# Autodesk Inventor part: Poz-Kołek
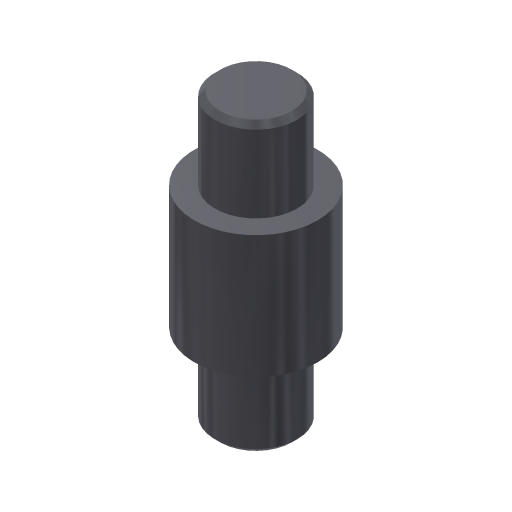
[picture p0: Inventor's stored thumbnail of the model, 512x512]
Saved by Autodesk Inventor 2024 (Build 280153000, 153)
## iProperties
Company: ATC
Shininess: 20.0
Angle Display Precision: 2
Document Length Units: 11269
Document Angle Units: 11279
Document Time Units: 11290
Document Mass Units: 11283
Document Length Units Precision: 3
Document Angle Units Precision: 2
Created: 2023-03
Part Number: Poz-Kołek
Material: Standardowy
Document SubType Name: Modelowanie
Designer: Andrzej Jaskulski
Density: 1 g/cm^3
Appearance: Metal-stal (polerowana)
Checked By: A.J.
Engr Approved By: Andrzej Jaskulski
Mfg Approved By: Andrzej Jaskulski
Authority: A.J.
Density: 0.0
Volumn: 0.0
Area: 0.0
PropertySet Name: Model Information
Control State: 0
Master: False
Checked Out: False
Title: A.J.: Kurs R2024-MEP
Author: Andrzej Jaskulski
Revision Number: 1/24
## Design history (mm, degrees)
node "Początek"
  node "Płaszczyzna YZ"
  node "Płaszczyzna XZ"
  node "Płaszczyzna XY"
  node "Oś X"
  node "Oś Y"
  node "Oś Z"
sketch "Szkic1"
  geometry: C1 r 4 at (41.919, -38.642) reference; C2 r 6 at (41.919, -38.642)
  constraints: 1 centre point, 1 coincident
  dimensions: "d0" = 2 radial gap between concentric circles of C2 C1
extrude "Wyciągnięcie proste1" new body sketch "Szkic1" distance "d1" = 12; taper "d2" = 0 deg
extrude "Wyciągnięcie proste2" join sketch "Szkic1" distance "d3" = 8; taper "d4" = 0 deg
node "Płaszczyzna konstrukcyjna1"
chamfer "Faza1" distance "d6" = 0.5; stored, may be unused: second distance "d7" = 0.5, angle "d9" = 45 deg
mirror "Lustro1"
node "Bryła1"
node "Korpusy bryłowe"
node "Korpusy powierzchniowe"
node "Punkt środkowy"
other parameters: "d5" = -6 (= -0.5 x d1), "d8" = 0
